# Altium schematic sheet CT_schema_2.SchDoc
size 398 x 262 mm
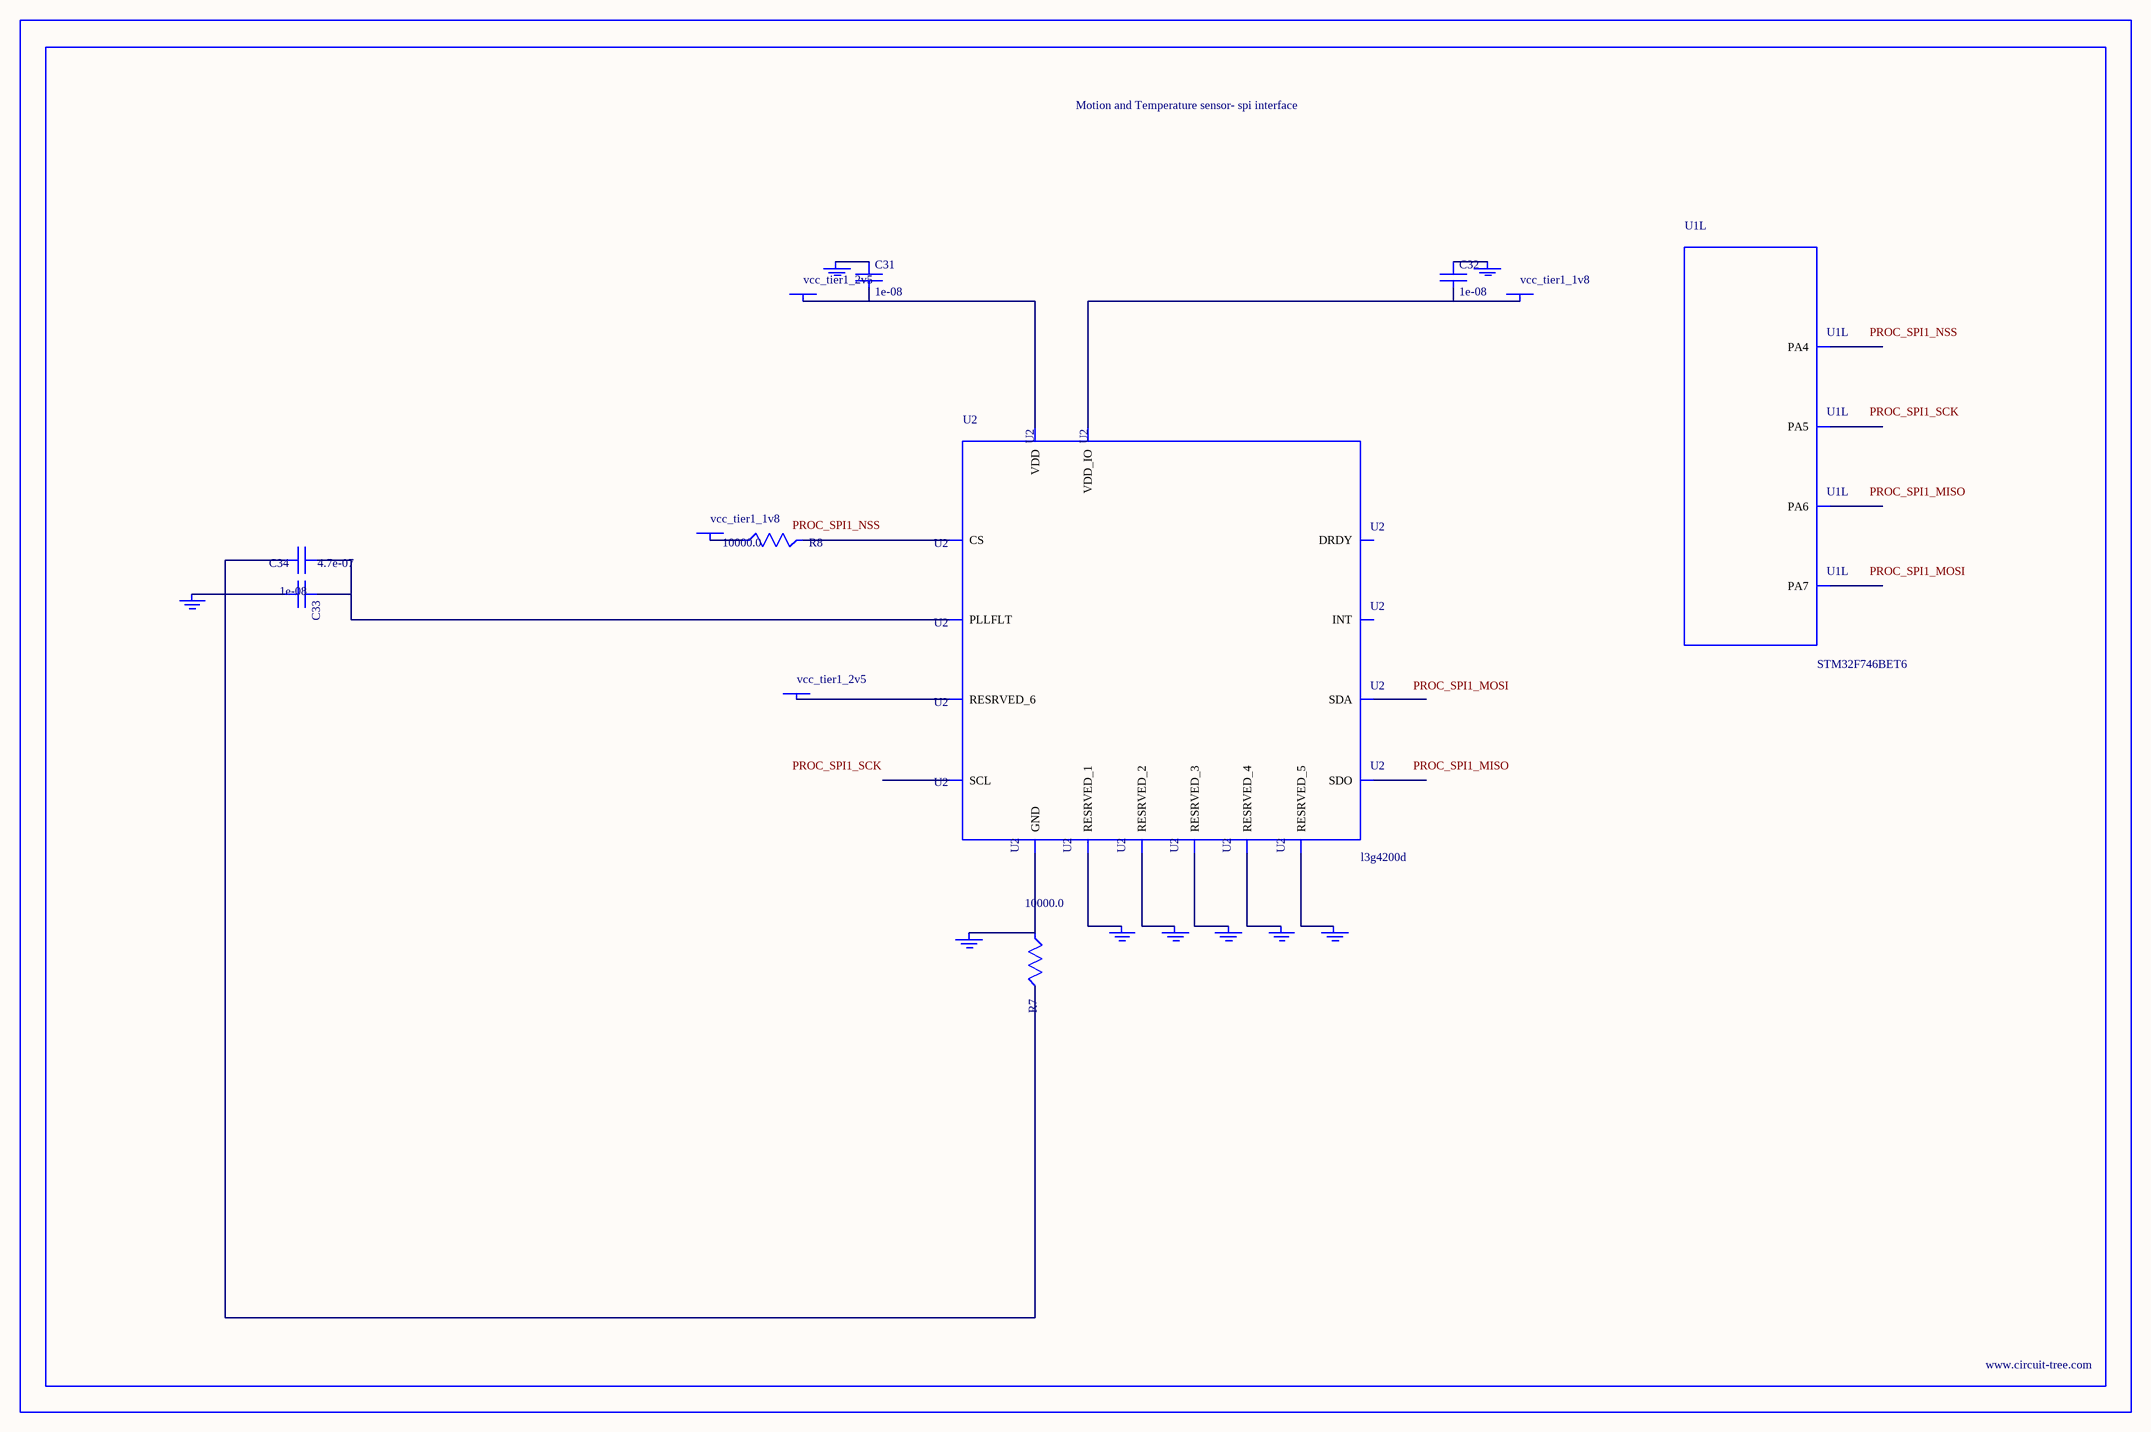
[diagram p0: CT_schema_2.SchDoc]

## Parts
BORDER1  (no value)
C31  1e-08  [C0402]
C32  1e-08  [C0402]
C33  1e-08  [C0402]
C34  4.7e-07  [C0603]
GND_INSTANCE_1_0  (no value)
GND_INSTANCE_1_1  (no value)
GND_INSTANCE_1_2  (no value)
GND_INSTANCE_1_3  (no value)
GND_INSTANCE_1_4  (no value)
GND_INSTANCE_1_5  (no value)
GND_INSTANCE_1_6  (no value)
GND_INSTANCE_1_7  (no value)
GND_INSTANCE_1_8  (no value)
POWER_INSTANCE_1_0  vcc_tier1_1v8
POWER_INSTANCE_1_1  vcc_tier1_1v8
POWER_INSTANCE_1_2  vcc_tier1_2v5
POWER_INSTANCE_1_3  vcc_tier1_2v5
R7  10000.0  [R0603]
R8  10000.0  [R0603]
U1  STM32F746BET6  [LQFP208]  (part L of 15)
U2  l3g4200d  [LGA-16]

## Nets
NetC31_1: C31.1 GND_INSTANCE_1_8.0(GND)
NetC31_2: C31.2 POWER_INSTANCE_1_3.0(PWR) U2.16(VDD)
NetC32_1: C32.1 GND_INSTANCE_1_0.0(GND)
NetC32_2: C32.2 POWER_INSTANCE_1_0.0(PWR) U2.1(VDD_IO)
NetC33_1: C33.1 C34.1 U2.14(PLLFLT)
NetC33_2: C33.2 C34.2 GND_INSTANCE_1_7.0(GND) R7.2
NetGND_INSTANCE_1_1_0: GND_INSTANCE_1_1.0(GND) U2.8(RESRVED_1)
NetGND_INSTANCE_1_2_0: GND_INSTANCE_1_2.0(GND) U2.9(RESRVED_2)
NetGND_INSTANCE_1_3_0: GND_INSTANCE_1_3.0(GND) U2.10(RESRVED_3)
NetGND_INSTANCE_1_4_0: GND_INSTANCE_1_4.0(GND) U2.11(RESRVED_4)
NetGND_INSTANCE_1_5_0: GND_INSTANCE_1_5.0(GND) U2.12(RESRVED_5)
NetGND_INSTANCE_1_6_0: GND_INSTANCE_1_6.0(GND) R7.1 U2.13(GND)
NetPOWER_INSTANCE_1_1_0: POWER_INSTANCE_1_1.0(PWR) R8.1
NetPOWER_INSTANCE_1_2_0: POWER_INSTANCE_1_2.0(PWR) U2.15(RESRVED_6)
NetR8_2: R8.2 U2.5(CS)

Not connected (* = marked no-connect by the designer): U1 53(PA4) 54(PA5) 55(PA6) 56(PA7); U2 2(SCL) 3(SDA) 4(SDO) 6(DRDY) 7(INT)

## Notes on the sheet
- Labels drawn without touching a wire or pin: PROC_SPI1_MISO, PROC_SPI1_MOSI, PROC_SPI1_NSS, PROC_SPI1_SCK

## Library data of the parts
BORDER1 = BORDER_PAGE1
C31-C33 = C0402C103K3RAC
C34 = C0603C474K3RAC
GND_INSTANCE_1_0-GND_INSTANCE_1_8 = GND
POWER_INSTANCE_1_0-POWER_INSTANCE_1_3 = PWR
R7 R8 = RC0603JR-0710KL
